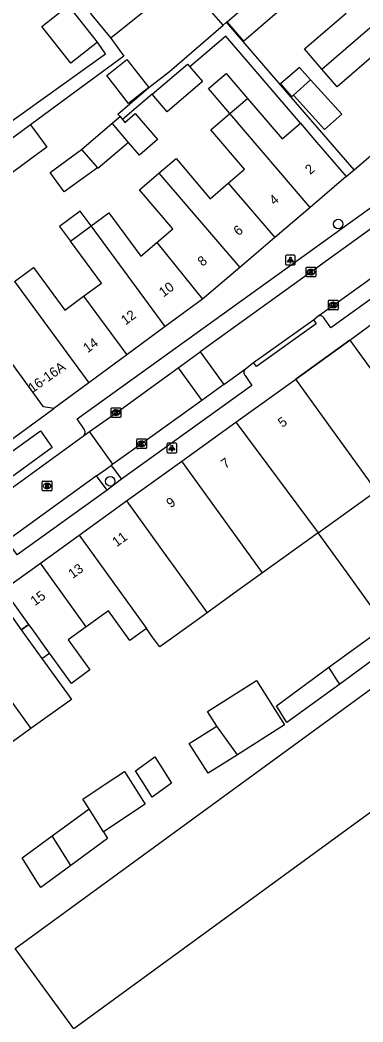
# Model space of a CAD drawing. Extents: x 161882 to 162509, y 381687 to 382379.
# Drawn here: x 162276 to 162311.3, y 381877.6 to 381980.9 of the extents above; entities that cross this region are included whole.
import ezdxf

# ---------------------------------------------------------------- set-up
doc = ezdxf.new("R2010")
doc.units = 0
for name, color, linetype in [('IMGEO_Boom', 7, 'Continuous'), ('IMGEO_Kolk', 7, 'Continuous'), ('IMGEO_Lichtpunt', 7, 'Continuous'), ('IMGEO_Muur', 7, 'Continuous'), ('IMGEO_Pand', 7, 'Continuous'), ('IMGEO_Pand_nummerreeks', 7, 'Continuous'), ('IMGEO_Pand_overbouw', 7, 'Continuous'), ('IMGEO_Parkeervlak_open', 7, 'Continuous'), ('IMGEO_Rijbaan_lokaal_open', 7, 'Continuous'), ('IMGEO_Rioolput', 7, 'Continuous'), ('IMGEO_Voetpad_open', 7, 'Continuous')]:
    doc.layers.add(name, color=color, linetype=linetype)

msp = doc.modelspace()

# ---------------------------------------------------------------- linework, layer by layer
at = {"layer": 'IMGEO_Boom'}
for centre in [(162308.8, 381959.89), (162285.31, 381933.37)]:
    msp.add_circle(centre, 0.489, dxfattribs=at)
at = {"layer": 'IMGEO_Kolk'}
for p, q in [((162305.49, 381954.52), (162305.49, 381955.37)), ((162305.56, 381955.44), (162306.42, 381955.44)), ((162306.49, 381955.37), (162306.49, 381954.52)), ((162306.42, 381954.44), (162305.56, 381954.44)), ((162306, 381954.66), (162305.97, 381954.66)), ((162305.98, 381955.22), (162306, 381955.22)), ((162307.79, 381951.11), (162307.79, 381951.96)), ((162307.87, 381952.04), (162308.72, 381952.04)), ((162308.28, 381951.82), (162308.31, 381951.82)), ((162308.3, 381951.26), (162308.28, 381951.26)), ((162308.79, 381951.96), (162308.79, 381951.11)), ((162308.72, 381951.04), (162307.87, 381951.04)), ((162285.41, 381940.02), (162285.41, 381940.87)), ((162285.48, 381940.95), (162286.34, 381940.95)), ((162286.41, 381940.87), (162286.41, 381940.02)), ((162286.34, 381939.95), (162285.48, 381939.95)), ((162285.9, 381940.73), (162285.92, 381940.73)), ((162285.92, 381940.17), (162285.9, 381940.17)), ((162288.04, 381936.81), (162288.04, 381937.66)), ((162288.12, 381937.74), (162288.97, 381937.74)), ((162288.97, 381936.74), (162288.12, 381936.74)), ((162288.53, 381937.52), (162288.56, 381937.52)), ((162288.55, 381936.96), (162288.53, 381936.96)), ((162289.05, 381937.66), (162289.05, 381936.81))]:
    msp.add_line(p, q, dxfattribs=at)
for points in [[(162305.49, 381954.52), (162305.49, 381955.37)], [(162305.56, 381955.44), (162306.42, 381955.44)], [(162306.49, 381955.37), (162306.49, 381954.52)], [(162306.42, 381954.44), (162305.56, 381954.44)], [(162305.81, 381955.14), (162305.93, 381955.14), (162305.93, 381954.99), (162306.06, 381955.14), (162306.23, 381955.14), (162306.08, 381954.99), (162306.23, 381954.74), (162306.08, 381954.74), (162306, 381954.91), (162305.93, 381954.84), (162305.93, 381954.74), (162305.81, 381954.74), (162305.81, 381955.14)], [(162307.79, 381951.11), (162307.79, 381951.96)], [(162307.87, 381952.04), (162308.72, 381952.04)], [(162308.11, 381951.74), (162308.24, 381951.74), (162308.24, 381951.59), (162308.37, 381951.74), (162308.53, 381951.74), (162308.39, 381951.59), (162308.54, 381951.34), (162308.39, 381951.34), (162308.3, 381951.5), (162308.24, 381951.44), (162308.24, 381951.34), (162308.11, 381951.34), (162308.11, 381951.74)], [(162308.79, 381951.96), (162308.79, 381951.11)], [(162308.72, 381951.04), (162307.87, 381951.04)], [(162285.41, 381940.02), (162285.41, 381940.87)], [(162285.48, 381940.95), (162286.34, 381940.95)], [(162286.41, 381940.87), (162286.41, 381940.02)], [(162286.34, 381939.95), (162285.48, 381939.95)], [(162285.73, 381940.65), (162285.85, 381940.65), (162285.85, 381940.5), (162285.98, 381940.65), (162286.15, 381940.65), (162286, 381940.5), (162286.15, 381940.25), (162286, 381940.25), (162285.92, 381940.41), (162285.85, 381940.34), (162285.85, 381940.25), (162285.73, 381940.25), (162285.73, 381940.65)], [(162288.04, 381936.81), (162288.04, 381937.66)], [(162288.12, 381937.74), (162288.97, 381937.74)], [(162288.97, 381936.74), (162288.12, 381936.74)], [(162288.36, 381937.44), (162288.49, 381937.44), (162288.49, 381937.28), (162288.62, 381937.44), (162288.78, 381937.44), (162288.64, 381937.29), (162288.79, 381937.04), (162288.64, 381937.04), (162288.55, 381937.2), (162288.49, 381937.13), (162288.49, 381937.04), (162288.36, 381937.04), (162288.36, 381937.44)], [(162289.05, 381937.66), (162289.05, 381936.81)]]:
    msp.add_lwpolyline(points, dxfattribs=at)
for centre, start, end in [((162305.57, 381955.37), 91.552, 178.448), ((162305.57, 381955.37), 91.552, 178.448), ((162306.41, 381955.37), 1.552, 88.448), ((162306.41, 381955.37), 1.552, 88.448), ((162305.57, 381954.52), 181.552, 268.448), ((162305.57, 381954.52), 181.552, 268.448), ((162306.41, 381954.52), 271.552, 358.448), ((162306.41, 381954.52), 271.552, 358.448), ((162307.87, 381951.96), 91.552, 178.448), ((162307.87, 381951.96), 91.552, 178.448), ((162308.72, 381951.96), 1.552, 88.448), ((162308.72, 381951.96), 1.552, 88.448), ((162307.87, 381951.11), 181.552, 268.448), ((162307.87, 381951.11), 181.552, 268.448), ((162308.72, 381951.11), 271.552, 358.448), ((162308.72, 381951.11), 271.552, 358.448), ((162285.49, 381940.87), 91.552, 178.448), ((162285.49, 381940.87), 91.552, 178.448), ((162286.33, 381940.87), 1.552, 88.448), ((162286.33, 381940.87), 1.552, 88.448), ((162285.49, 381940.02), 181.552, 268.448), ((162285.49, 381940.02), 181.552, 268.448), ((162286.33, 381940.02), 271.552, 358.448), ((162286.33, 381940.02), 271.552, 358.448), ((162288.12, 381937.66), 91.552, 178.448), ((162288.12, 381937.66), 91.552, 178.448), ((162288.12, 381936.81), 181.552, 268.448), ((162288.12, 381936.81), 181.552, 268.448), ((162288.97, 381937.66), 1.552, 88.448), ((162288.97, 381937.66), 1.552, 88.448), ((162288.97, 381936.81), 271.552, 358.448), ((162288.97, 381936.81), 271.552, 358.448)]:
    msp.add_arc(centre, 0.0765, start, end, dxfattribs=at)
for centre, major_axis, ratio, start_param, end_param in [((162305.98, 381954.94), (-0.387, 0.002), 0.722429, 4.712389, 7.853982), ((162306, 381954.94), (-0.39, 0.002), 0.717154, 1.570796, 4.712389), ((162308.28, 381951.54), (-0.387, 0.002), 0.722429, 4.712389, 7.853982), ((162308.3, 381951.54), (-0.39, 0.002), 0.717154, 1.570796, 4.712389), ((162285.9, 381940.45), (-0.387, 0.002), 0.722429, 4.712389, 7.853982), ((162285.92, 381940.45), (-0.39, 0.002), 0.717154, 1.570796, 4.712389), ((162288.53, 381937.24), (-0.387, 0.002), 0.722429, 4.712389, 7.853982), ((162288.56, 381937.24), (-0.39, 0.002), 0.717154, 1.570796, 4.712389)]:
    msp.add_ellipse(centre, major_axis=major_axis, ratio=ratio, start_param=start_param, end_param=end_param, dxfattribs=at)
at = {"layer": 'IMGEO_Lichtpunt'}
for p, q in [((162303.37, 381956.58), (162303.37, 381955.77)), ((162303.37, 381956.58), (162303.37, 381955.77)), ((162304.28, 381956.67), (162303.47, 381956.67)), ((162304.28, 381956.67), (162303.47, 381956.67)), ((162304.37, 381955.77), (162304.37, 381956.58)), ((162304.37, 381955.77), (162304.37, 381956.58)), ((162303.47, 381955.67), (162304.28, 381955.67)), ((162303.47, 381955.67), (162304.28, 381955.67)), ((162291.16, 381937.2), (162291.16, 381936.39)), ((162291.16, 381937.2), (162291.16, 381936.39)), ((162292.07, 381937.29), (162291.26, 381937.29)), ((162292.07, 381937.29), (162291.26, 381937.29)), ((162292.16, 381936.39), (162292.16, 381937.2)), ((162292.16, 381936.39), (162292.16, 381937.2)), ((162291.26, 381936.3), (162292.07, 381936.3)), ((162291.26, 381936.3), (162292.07, 381936.3))]:
    msp.add_line(p, q, dxfattribs=at)
for points in [[(162303.75, 381956.24), (162303.79, 381956.21), (162303.6, 381955.95), (162303.56, 381955.98), (162303.75, 381956.24)], [(162303.85, 381956.19), (162303.9, 381956.19), (162303.9, 381955.87), (162303.85, 381955.87), (162303.85, 381956.19)], [(162303.96, 381956.21), (162304, 381956.24), (162304.18, 381955.98), (162304.15, 381955.95), (162303.96, 381956.21)], [(162291.54, 381936.86), (162291.58, 381936.84), (162291.39, 381936.57), (162291.35, 381936.6), (162291.54, 381936.86)], [(162291.64, 381936.82), (162291.69, 381936.82), (162291.69, 381936.49), (162291.64, 381936.49), (162291.64, 381936.82)], [(162291.75, 381936.84), (162291.79, 381936.86), (162291.98, 381936.6), (162291.94, 381936.57), (162291.75, 381936.84)]]:
    msp.add_lwpolyline(points, dxfattribs=at)
for centre in [(162303.87, 381956.37), (162291.66, 381937)]:
    msp.add_circle(centre, 0.0994, dxfattribs=at)
for centre, start, end in [((162303.47, 381956.58), 90, 180), ((162303.47, 381956.58), 90, 180), ((162304.28, 381956.58), 0, 90), ((162304.28, 381956.58), 0, 90), ((162303.47, 381955.77), 180, 270), ((162303.47, 381955.77), 180, 270), ((162304.28, 381955.77), 270, 0), ((162304.28, 381955.77), 270, 360), ((162291.26, 381937.2), 90, 180), ((162291.26, 381937.2), 90, 180), ((162292.07, 381937.2), 0, 90), ((162292.07, 381937.2), 0, 90), ((162291.26, 381936.39), 180, 270), ((162291.26, 381936.39), 180, 270), ((162292.07, 381936.39), 270, 0), ((162292.07, 381936.39), 270, 360)]:
    msp.add_arc(centre, 0.0946, start, end, dxfattribs=at)
at = {"layer": 'IMGEO_Muur'}
msp.add_lwpolyline([(162309.98, 381947.93), (162304.44, 381943.91)], dxfattribs=at)
at = {"layer": 'IMGEO_Pand'}
for points in [[(162297.35, 381980.75), (162300.54, 381983.52), (162310.16, 381991.83)], [(162296.95, 381980.4), (162295.27, 381982.33), (162298.87, 381985.46), (162303.18, 381989.17), (162301.78, 381990.79)], [(162284.21, 381982.81), (162286.55, 381984.69), (162288.84, 381981.84), (162285.36, 381979.04)], [(162308.14, 381983.37), (162306.56, 381985.2), (162302.27, 381981.5), (162299.08, 381978.75), (162297.35, 381980.75)], [(162307.12, 381975.87), (162305.34, 381977.94), (162309.63, 381981.63), (162308.14, 381983.37)], [(162307.12, 381975.87), (162316.76, 381984.19)], [(162283.99, 381978.64), (162281.27, 381976.48), (162278.28, 381980.25), (162281, 381982.41)], [(162283.99, 381978.64), (162281, 381982.41)], [(162284.21, 381982.81), (162283.06, 381981.89), (162283.43, 381981.43), (162285.36, 381979.04)], [(162297.3, 381980.7), (162296.95, 381980.4)], [(162297.35, 381980.75), (162297.3, 381980.7)], [(162314.63, 381975.84), (162312.98, 381977.75), (162308.69, 381974.05), (162307.12, 381975.87)], [(162289.3, 381973.96), (162287.21, 381972.32), (162284.95, 381975.2), (162287.04, 381976.84), (162289.3, 381973.96)], [(162289.63, 381973.27), (162293.27, 381976.38), (162293.51, 381976.1)], [(162293.51, 381976.1), (162294.81, 381974.57), (162291.18, 381971.46), (162289.63, 381973.27)], [(162305.95, 381974.75), (162304.8, 381976.01), (162302.86, 381974.34), (162303.92, 381973.11), (162303.98, 381973.04), (162304.18, 381973.19)], [(162297.64, 381971.27), (162295.43, 381973.85), (162297.26, 381975.41), (162299.47, 381972.83)], [(162304.18, 381973.19), (162305.95, 381974.75)], [(162305.95, 381974.75), (162309.16, 381971.23), (162307.38, 381969.65), (162304.18, 381973.19)], [(162297.64, 381971.27), (162299.47, 381972.83)], [(162299.47, 381972.83), (162303.01, 381968.68), (162304.9, 381970.29)], [(162285.53, 381970.28), (162286.33, 381970.97)], [(162286.33, 381970.97), (162286.58, 381970.66)], [(162286.58, 381970.66), (162286.83, 381970.37), (162287.9, 381971.29), (162290.19, 381968.59), (162288.32, 381967), (162287.2, 381968.31)], [(162297.48, 381964.09), (162299.16, 381965.53), (162295.68, 381969.6), (162297.64, 381971.27)], [(162305.9, 381961.61), (162297.64, 381971.27)], [(162277.11, 381970.11), (162273.12, 381967.18), (162268.24, 381963.6), (162264.22, 381960.64)], [(162277.11, 381970.11), (162278.43, 381968.31), (162278.79, 381967.83), (162277.38, 381966.79), (162277.1, 381966.59), (162272.58, 381963.26), (162273.88, 381961.5)], [(162282.37, 381967.58), (162285.53, 381970.28)], [(162287.2, 381968.31), (162285.53, 381970.28)], [(162304.9, 381970.29), (162306.36, 381968.58), (162309.61, 381964.78)], [(162287.2, 381968.31), (162284.05, 381965.61), (162283.99, 381965.68)], [(162283.99, 381965.68), (162280.58, 381963.2), (162279.12, 381965.21), (162282.37, 381967.58)], [(162282.37, 381967.58), (162283.99, 381965.68)], [(162290.33, 381965.13), (162292.09, 381966.63), (162295.62, 381962.5), (162297.48, 381964.09)], [(162290.11, 381957.99), (162291.76, 381959.4), (162288.33, 381963.42), (162290.33, 381965.13)], [(162290.33, 381965.13), (162298.65, 381955.41)], [(162309.61, 381964.78), (162305.9, 381961.61)], [(162297.48, 381964.09), (162302.26, 381958.5)], [(162305.9, 381961.61), (162302.26, 381958.5)], [(162283.35, 381959.69), (162282.23, 381961.22), (162280.1, 381959.65), (162281.22, 381958.13)], [(162283.35, 381959.69), (162285.17, 381961.04), (162288.45, 381956.58), (162290.11, 381957.99)], [(162281.22, 381958.13), (162283.35, 381959.69)], [(162290.98, 381949.32), (162283.35, 381959.69)], [(162302.26, 381958.5), (162298.65, 381955.41)], [(162282.57, 381952.45), (162284.4, 381953.8), (162281.22, 381958.13)], [(162290.11, 381957.99), (162294.83, 381952.15)], [(162279.51, 381940.88), (162278.43, 381941.04), (162267.8, 381955.67)], [(162275.44, 381953.95), (162277.41, 381955.4), (162280.63, 381951.02), (162282.57, 381952.45)], [(162298.65, 381955.41), (162294.83, 381952.15)], [(162275.44, 381953.95), (162283.11, 381943.53)], [(162282.57, 381952.45), (162287.02, 381946.4)], [(162294.83, 381952.15), (162290.98, 381949.32)], [(162309.98, 381947.93), (162314.43, 381951.17)], [(162290.98, 381949.32), (162287.02, 381946.4)], [(162309.98, 381947.93), (162314.99, 381941.04), (162314.81, 381940.91), (162315.04, 381940.58), (162315.82, 381941.14), (162318.77, 381938.79), (162321.83, 381941.02)], [(162287.02, 381946.4), (162283.11, 381943.53)], [(162283.11, 381943.53), (162279.51, 381940.88)], [(162298.26, 381939.46), (162304.44, 381943.91)], [(162312.35, 381932.92), (162307.36, 381939.85), (162304.44, 381943.91)], [(162292.69, 381935.44), (162298.26, 381939.46)], [(162298.26, 381939.46), (162306.73, 381928.06)], [(162287, 381931.34), (162292.69, 381935.44)], [(162300.99, 381923.92), (162292.69, 381935.44)], [(162306.73, 381928.06), (162312.74, 381932.39), (162312.35, 381932.92)], [(162282.12, 381927.82), (162287, 381931.34)], [(162287, 381931.34), (162291.49, 381925.1), (162291.69, 381924.82), (162293.55, 381922.24), (162294.23, 381921.29), (162295.29, 381919.82)], [(162278.12, 381924.94), (162282.12, 381927.82)], [(162282.12, 381927.82), (162289.05, 381918.2)], [(162306.73, 381928.06), (162300.99, 381923.92)], [(162314.84, 381916.85), (162314.64, 381917.09), (162309.64, 381924.03), (162306.73, 381928.06)], [(162274.34, 381922.22), (162278.12, 381924.94)], [(162282.84, 381918.38), (162278.12, 381924.94)], [(162300.99, 381923.92), (162298.47, 381922.11), (162295.29, 381919.82)], [(162273.55, 381921.65), (162276.15, 381918.05), (162276.48, 381917.59), (162278.28, 381915.09), (162280.53, 381911.97), (162280.9, 381911.45), (162281.31, 381910.88), (162277.15, 381907.89)], [(162282.84, 381918.38), (162280.98, 381917.04), (162283.23, 381913.92), (162281.31, 381912.54), (162279.06, 381915.66), (162277.26, 381918.16), (162276.93, 381918.62), (162274.34, 381922.22)], [(162289.05, 381918.2), (162287.34, 381916.96), (162285.13, 381920.03), (162282.84, 381918.38)], [(162295.29, 381919.82), (162294.15, 381918.99), (162290.41, 381916.3), (162290.27, 381916.49), (162289.68, 381917.31), (162289.05, 381918.2)], [(162269.4, 381918.66), (162274.13, 381912.09), (162277.15, 381907.89)], [(162307.85, 381914.2), (162313.43, 381918.27), (162313.69, 381917.87), (162313.88, 381917.57), (162314.53, 381916.54), (162308.95, 381912.47)], [(162308.95, 381912.47), (162303.52, 381908.51), (162302.43, 381910.24), (162307.85, 381914.2)], [(162308.95, 381912.47), (162308.67, 381912.91), (162308.14, 381913.74), (162308.02, 381913.94), (162307.85, 381914.2)], [(162320.51, 381888.58), (162315.64, 381894.33), (162318.48, 381896.73), (162315.07, 381901.39), (162281.55, 381876.92), (162275.51, 381885.2), (162313.12, 381912.66), (162318.99, 381904.64), (162322.76, 381907.39)], [(162296.29, 381908.13), (162295.33, 381909.64), (162300.39, 381912.84), (162303.28, 381908.26), (162298.41, 381905.18)], [(162277.15, 381907.89), (162273.19, 381905.03)], [(162298.41, 381905.18), (162295.39, 381903.27), (162293.45, 381906.33), (162296.29, 381908.13)], [(162298.41, 381905.18), (162296.29, 381908.13)], [(162287.92, 381903.53), (162289.9, 381904.97), (162290.69, 381903.72), (162291.61, 381902.26), (162289.64, 381900.82), (162288.71, 381902.28), (162287.92, 381903.53)], [(162283.13, 381899.6), (162282.48, 381900.62), (162284.5, 381901.96), (162284.79, 381902.15), (162286.79, 381903.47), (162286.97, 381903.18), (162288.93, 381900.09), (162284.62, 381897.24)], [(162279.33, 381896.81), (162283.13, 381899.6)], [(162284.62, 381897.24), (162283.13, 381899.6)], [(162281.25, 381893.77), (162278.15, 381891.5), (162277.83, 381892.02), (162277.66, 381892.28), (162276.23, 381894.54), (162279.33, 381896.81)], [(162281.25, 381893.77), (162279.33, 381896.81)], [(162284.62, 381897.24), (162285.05, 381896.55), (162281.25, 381893.77)]]:
    msp.add_lwpolyline(points, dxfattribs=at)
at = {"layer": 'IMGEO_Pand_overbouw'}
for points in [[(162276.15, 381918.05), (162276.93, 381918.62), (162274.34, 381922.22), (162273.55, 381921.65)], [(162276.93, 381918.62), (162276.15, 381918.05), (162276.48, 381917.59), (162278.28, 381915.09), (162279.06, 381915.66), (162277.26, 381918.16)]]:
    msp.add_lwpolyline(points, close=True, dxfattribs=at)
at = {"layer": 'IMGEO_Parkeervlak_open'}
for points in [[(162285.4, 381934.99), (162286.49, 381933.58)], [(162284.99, 381932.45), (162283.9, 381933.94)]]:
    msp.add_lwpolyline(points, dxfattribs=at)
at = {"layer": 'IMGEO_Rijbaan_lokaal_open'}
for points in [[(162324.7, 381968.44), (162323.4, 381967.5), (162305.99, 381954.94), (162294.59, 381946.71)], [(162306.7, 381950.39), (162308.3, 381951.54), (162326.21, 381964.39), (162330.08, 381967.22)], [(162306.24, 381950.01), (162306.7, 381950.39)], [(162300.08, 381945.6), (162306.24, 381950.01)], [(162292.32, 381945.07), (162294.59, 381946.71)], [(162294.59, 381946.71), (162297.01, 381943.35)], [(162283.17, 381938.49), (162285.91, 381940.44), (162292.32, 381945.07)], [(162292.32, 381945.07), (162294.74, 381941.71)], [(162299.26, 381944.97), (162300.08, 381945.6)], [(162297.01, 381943.35), (162299.26, 381944.97)], [(162297.01, 381943.35), (162294.74, 381941.71)], [(162269.88, 381933.87), (162279.51, 381940.88)], [(162294.74, 381941.71), (162288.55, 381937.24), (162285.58, 381935.12)], [(162271.2, 381929.81), (162282.55, 381938.05)], [(162279.33, 381936.84), (162273.45, 381932.6), (162272.2, 381934.3), (162278.12, 381938.56), (162279.33, 381936.84)], [(162282.55, 381938.05), (162283.17, 381938.49)], [(162285.58, 381935.12), (162283.17, 381938.49)], [(162283.9, 381933.94), (162285.4, 381934.99)], [(162285.58, 381935.12), (162285.4, 381934.99)], [(162283.9, 381933.94), (162274.28, 381926.96)]]:
    msp.add_lwpolyline(points, dxfattribs=at)
at = {"layer": 'IMGEO_Rioolput'}
for p, q in [((162278.31, 381932.47), (162278.31, 381933.32)), ((162278.38, 381933.39), (162279.24, 381933.39)), ((162278.82, 381932.61), (162278.79, 381932.61)), ((162278.8, 381933.17), (162278.82, 381933.17)), ((162279.31, 381933.32), (162279.31, 381932.47)), ((162279.24, 381932.39), (162278.38, 381932.39))]:
    msp.add_line(p, q, dxfattribs=at)
for points in [[(162278.31, 381932.47), (162278.31, 381933.32)], [(162278.38, 381933.39), (162279.24, 381933.39)], [(162278.9, 381933.09), (162278.65, 381933.09), (162278.65, 381932.69)], [(162278.65, 381932.69), (162278.77, 381932.69), (162278.77, 381932.86), (162278.78, 381932.86)], [(162278.82, 381933.01), (162278.77, 381933.01), (162278.77, 381932.93)], [(162278.77, 381932.93), (162278.82, 381932.93)], [(162278.83, 381932.83), (162278.9, 381932.69), (162279.04, 381932.69), (162278.97, 381932.82)], [(162279.31, 381933.32), (162279.31, 381932.47)], [(162279.24, 381932.39), (162278.38, 381932.39)]]:
    msp.add_lwpolyline(points, dxfattribs=at)
for centre, radius, start, end in [((162278.39, 381933.32), 0.0765, 91.552, 178.448), ((162278.39, 381933.32), 0.0765, 91.552, 178.448), ((162278.78, 381932.8), 0.0533, 26.0293, 88.6989), ((162278.83, 381932.92), 0.0964, 77.0061, 93.1865), ((162278.81, 381933.12), 0.19, 274.7715, 282.9687), ((162278.84, 381932.97), 0.0378, 276.6634, 79.6772), ((162278.9, 381932.98), 0.109, 350.3612, 89.416), ((162278.9, 381932.98), 0.112, 277.5842, 350.9817), ((162278.88, 381932.77), 0.108, 29.5134, 73.7905), ((162279.23, 381933.32), 0.0765, 1.552, 88.448), ((162279.23, 381933.32), 0.0765, 1.552, 88.448), ((162278.39, 381932.47), 0.0765, 181.552, 268.448), ((162278.39, 381932.47), 0.0765, 181.552, 268.448), ((162279.23, 381932.47), 0.0765, 271.552, 358.448), ((162279.23, 381932.47), 0.0765, 271.552, 358.448)]:
    msp.add_arc(centre, radius, start, end, dxfattribs=at)
for centre, major_axis, ratio, start_param, end_param in [((162278.8, 381932.89), (-0.387, 0.002), 0.722429, 4.712389, 7.853982), ((162278.82, 381932.89), (-0.39, 0.002), 0.717154, 1.570796, 4.712389)]:
    msp.add_ellipse(centre, major_axis=major_axis, ratio=ratio, start_param=start_param, end_param=end_param, dxfattribs=at)
at = {"layer": 'IMGEO_Voetpad_open'}
for points in [[(162289.3, 381973.96), (162291.42, 381975.63), (162296.95, 381980.4)], [(162310.44, 381965.49), (162303.52, 381973.5), (162297.3, 381980.7)], [(162304.9, 381970.29), (162297.22, 381979.27), (162293.51, 381976.1)], [(162271.96, 381968.23), (162284.82, 381977.45), (162283.99, 381978.64)], [(162285.36, 381979.04), (162286.72, 381977.19), (162281.17, 381973.1), (162277.11, 381970.11)], [(162286.33, 381970.97), (162286.1, 381971.23), (162289.3, 381973.96)], [(162289.63, 381973.27), (162286.58, 381970.66)], [(162282.62, 381938.73), (162281.9, 381939.8), (162323.29, 381969.6), (162324.01, 381968.53)], [(162310.44, 381965.49), (162313.65, 381968.21)], [(162330.01, 381966.57), (162330.74, 381965.55), (162316.45, 381955.25), (162308.03, 381949.19), (162307.31, 381950.22)], [(162309.61, 381964.78), (162310.44, 381965.49)], [(162306.24, 381950.01), (162306.53, 381949.6), (162300.38, 381945.19), (162300.08, 381945.6)], [(162304.44, 381943.91), (162309.98, 381947.93)], [(162299.21, 381944.26), (162299.89, 381943.23), (162286.49, 381933.58)], [(162286.49, 381933.58), (162284.99, 381932.45)], [(162284.99, 381932.45), (162275.73, 381925.79), (162274.97, 381926.85)]]:
    msp.add_lwpolyline(points, dxfattribs=at)
for centre, radius, start, end in [((162306.92, 381950), 0.446, 28.7566, 119.3526), ((162299.56, 381944.59), 0.486, 128.1822, 222.8235), ((162282.26, 381938.43), 0.476, 308.064, 40.2154)]:
    msp.add_arc(centre, radius, start, end, dxfattribs=at)

# ---------------------------------------------------------------- texts
at = {"layer": 'IMGEO_Pand_nummerreeks'}
for s, rotation, p in [('2', 40.5081, (162305.91, 381964.93)), ('4', 40.5099, (162302.22, 381961.78)), ('6', 40.5099, (162298.53, 381958.62)), ('8', 40.5099, (162294.83, 381955.47)), ('10', 36.3419, (162290.79, 381952.31)), ('12', 36.3427, (162286.88, 381949.43)), ('14', 36.3419, (162282.98, 381946.56)), ('16-16A', 35.5692, (162277.31, 381942.45)), ('5', 35.7756, (162303.04, 381938.86)), ('7', 35.7772, (162297.17, 381934.62)), ('9', 35.7755, (162291.54, 381930.57)), ('11', 35.7755, (162285.97, 381926.56)), ('13', 35.7765, (162281.44, 381923.29)), ('15', 35.7755, (162277.55, 381920.49))]:
    msp.add_text(s, height=1, rotation=rotation, dxfattribs=at).set_placement(p)

doc.saveas('drawing.dxf')
